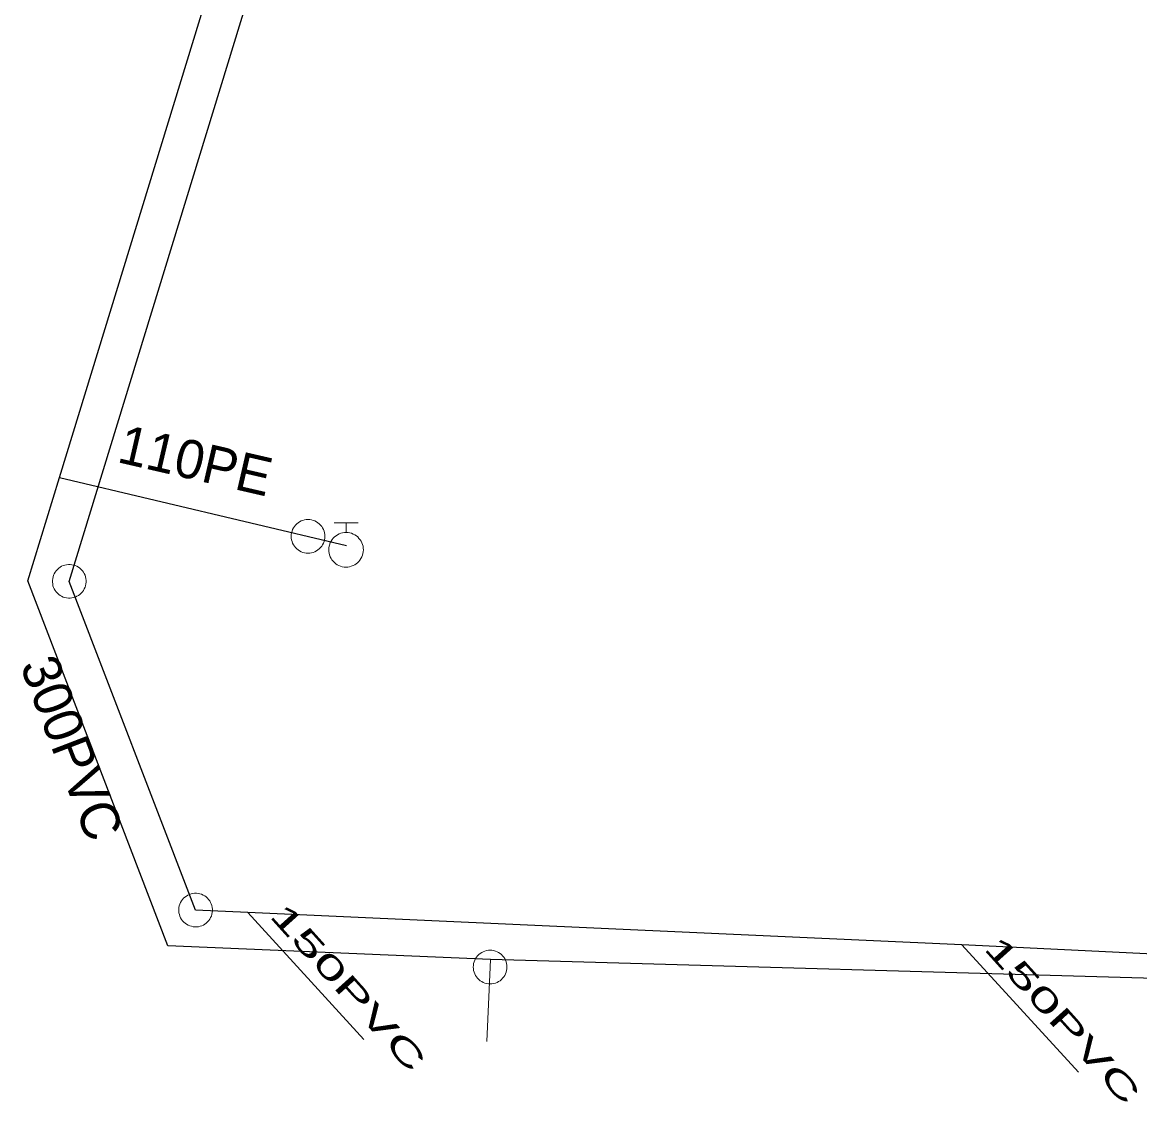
# Model space of a CAD drawing. Extents: x -741806 to -738704, y -1059275 to -1055387.
# Drawn here: x -740348.56 to -740319.54, y -1057396.67 to -1057368.63 of the extents above; entities that cross this region are included whole.
import ezdxf

# ---------------------------------------------------------------- set-up
doc = ezdxf.new("R2010")
doc.units = 0
doc.header["$LTSCALE"] = 0.4
for name, color, linetype, lineweight in [('2', 7, 'Continuous', 25), ('21', 7, 'Continuous', 13), ('3', 7, 'Continuous', 13), ('50', 7, 'Continuous', 13), ('51', 7, 'Continuous', 13), ('52', 7, 'Continuous', 25), ('56', 7, 'Continuous', 13)]:
    doc.layers.add(name, color=color, linetype=linetype, lineweight=lineweight)
for name, color, linetype in [('5', 7, 'Continuous'), ('53', 7, 'Continuous'), ('55', 7, 'Continuous')]:
    doc.layers.add(name, color=color, linetype=linetype)

msp = doc.modelspace()

# ---------------------------------------------------------------- linework, layer by layer
at = {"layer": '2'}
msp.add_line((-740344.059, -1057391.69), (-740347.34, -1057383.149), dxfattribs=at)
for points in [[(-740347.34, -1057383.149), (-740338.066, -1057352.864), (-740334.91, -1057342.56), (-740333.19, -1057336.94)], [(-740274.71, -1057394.48), (-740280.23, -1057394.279), (-740283.993, -1057394.142), (-740292.598, -1057393.83), (-740297.616, -1057393.647), (-740304.263, -1057393.406), (-740316.522, -1057392.96), (-740324.158, -1057392.594), (-740342.703, -1057391.752), (-740344.059, -1057391.69)]]:
    msp.add_lwpolyline(points, dxfattribs=at)
at = {"layer": '21'}
msp.add_lwpolyline([(-740336.401, -1057392.97), (-740336.41, -1057393.169), (-740336.495, -1057395.105)], dxfattribs=at)
at = {"layer": '3'}
for points in [[(-740347.496, -1057382.739), (-740347.537, -1057382.758), (-740347.577, -1057382.781), (-740347.614, -1057382.808), (-740347.648, -1057382.838), (-740347.678, -1057382.873), (-740347.706, -1057382.91), (-740347.728, -1057382.95), (-740347.747, -1057382.991), (-740347.761, -1057383.035), (-740347.77, -1057383.079), (-740347.775, -1057383.125), (-740347.776, -1057383.171), (-740347.77, -1057383.216), (-740347.762, -1057383.261), (-740347.747, -1057383.305), (-740347.729, -1057383.347), (-740347.705, -1057383.386), (-740347.679, -1057383.423), (-740347.648, -1057383.458), (-740347.613, -1057383.488), (-740347.576, -1057383.515), (-740347.538, -1057383.537), (-740347.495, -1057383.556), (-740347.452, -1057383.571), (-740347.407, -1057383.58), (-740347.361, -1057383.584), (-740347.316, -1057383.585), (-740347.27, -1057383.58), (-740347.225, -1057383.571), (-740347.181, -1057383.556), (-740347.14, -1057383.538), (-740347.101, -1057383.515), (-740347.063, -1057383.488), (-740347.029, -1057383.457), (-740346.999, -1057383.424), (-740346.971, -1057383.386), (-740346.949, -1057383.347), (-740346.93, -1057383.304), (-740346.916, -1057383.261), (-740346.907, -1057383.217), (-740346.902, -1057383.171), (-740346.901, -1057383.125), (-740346.906, -1057383.079), (-740346.916, -1057383.035), (-740346.93, -1057382.991), (-740346.949, -1057382.949), (-740346.971, -1057382.91), (-740346.998, -1057382.873), (-740347.029, -1057382.839), (-740347.064, -1057382.808), (-740347.101, -1057382.781), (-740347.14, -1057382.758), (-740347.182, -1057382.74), (-740347.225, -1057382.725), (-740347.27, -1057382.716), (-740347.316, -1057382.711), (-740347.361, -1057382.711), (-740347.408, -1057382.716), (-740347.452, -1057382.726), (-740347.495, -1057382.739)], [(-740344.496, -1057391.669), (-740344.495, -1057391.714), (-740344.49, -1057391.759), (-740344.48, -1057391.805), (-740344.466, -1057391.848), (-740344.447, -1057391.889), (-740344.424, -1057391.93), (-740344.396, -1057391.966), (-740344.366, -1057392), (-740344.331, -1057392.03), (-740344.295, -1057392.057), (-740344.255, -1057392.079), (-740344.212, -1057392.098), (-740344.169, -1057392.111), (-740344.124, -1057392.121), (-740344.078, -1057392.126), (-740344.032, -1057392.126), (-740343.987, -1057392.12), (-740343.943, -1057392.111), (-740343.899, -1057392.096), (-740343.857, -1057392.077), (-740343.818, -1057392.053), (-740343.782, -1057392.027), (-740343.747, -1057391.996), (-740343.717, -1057391.962), (-740343.69, -1057391.924), (-740343.668, -1057391.884), (-740343.649, -1057391.843), (-740343.635, -1057391.798), (-740343.626, -1057391.754), (-740343.622, -1057391.708), (-740343.622, -1057391.663), (-740343.627, -1057391.618), (-740343.637, -1057391.572), (-740343.652, -1057391.528), (-740343.67, -1057391.488), (-740343.693, -1057391.447), (-740343.72, -1057391.411), (-740343.752, -1057391.377), (-740343.786, -1057391.347), (-740343.822, -1057391.32), (-740343.862, -1057391.298), (-740343.905, -1057391.279), (-740343.948, -1057391.265), (-740343.993, -1057391.256), (-740344.038, -1057391.251), (-740344.085, -1057391.251), (-740344.13, -1057391.256), (-740344.174, -1057391.266), (-740344.218, -1057391.281), (-740344.26, -1057391.3), (-740344.299, -1057391.324), (-740344.336, -1057391.35), (-740344.37, -1057391.381), (-740344.4, -1057391.415), (-740344.427, -1057391.453), (-740344.45, -1057391.493), (-740344.468, -1057391.534), (-740344.482, -1057391.579), (-740344.491, -1057391.623), (-740344.496, -1057391.668)]]:
    msp.add_lwpolyline(points, dxfattribs=at)
at = {"layer": '50'}
for p in [(-740340.459, -1057381.626), (-740340.151, -1057381.879), (-740339.84, -1057381.626)]:
    msp.add_line(p, (-740340.151, -1057381.626), dxfattribs=at)
msp.add_lwpolyline([(-740339.703, -1057382.333), (-740339.704, -1057382.284), (-740339.711, -1057382.239), (-740339.723, -1057382.192), (-740339.738, -1057382.149), (-740339.757, -1057382.107), (-740339.784, -1057382.067), (-740339.816, -1057382.032), (-740339.847, -1057381.996), (-740339.884, -1057381.965), (-740339.925, -1057381.941), (-740339.966, -1057381.919), (-740340.008, -1057381.9), (-740340.054, -1057381.891), (-740340.101, -1057381.882), (-740340.147, -1057381.879), (-740340.192, -1057381.882), (-740340.24, -1057381.886), (-740340.287, -1057381.9), (-740340.329, -1057381.918), (-740340.374, -1057381.938), (-740340.412, -1057381.963), (-740340.45, -1057381.993), (-740340.483, -1057382.027), (-740340.512, -1057382.062), (-740340.539, -1057382.101), (-740340.56, -1057382.142), (-740340.577, -1057382.187), (-740340.593, -1057382.232), (-740340.597, -1057382.279), (-740340.602, -1057382.325), (-740340.6, -1057382.374), (-740340.593, -1057382.421), (-740340.581, -1057382.464), (-740340.565, -1057382.51), (-740340.542, -1057382.551), (-740340.519, -1057382.591), (-740340.487, -1057382.627), (-740340.456, -1057382.661), (-740340.418, -1057382.692), (-740340.38, -1057382.717), (-740340.335, -1057382.739), (-740340.293, -1057382.755), (-740340.249, -1057382.769), (-740340.2, -1057382.777), (-740340.153, -1057382.78), (-740340.106, -1057382.777), (-740340.062, -1057382.769), (-740340.016, -1057382.757), (-740339.971, -1057382.741), (-740339.928, -1057382.719), (-740339.889, -1057382.695), (-740339.852, -1057382.665), (-740339.819, -1057382.633), (-740339.79, -1057382.597), (-740339.765, -1057382.556), (-740339.739, -1057382.515), (-740339.724, -1057382.472), (-740339.712, -1057382.425), (-740339.704, -1057382.38)], close=True, dxfattribs=at)
at = {"layer": '51'}
for points in [[(-740340.701, -1057381.98), (-740340.703, -1057381.935), (-740340.711, -1057381.89), (-740340.723, -1057381.845), (-740340.739, -1057381.803), (-740340.76, -1057381.762), (-740340.784, -1057381.723), (-740340.814, -1057381.688), (-740340.846, -1057381.655), (-740340.882, -1057381.627), (-740340.919, -1057381.602), (-740340.961, -1057381.581), (-740341.004, -1057381.564), (-740341.048, -1057381.552), (-740341.093, -1057381.545), (-740341.139, -1057381.543), (-740341.184, -1057381.545), (-740341.23, -1057381.552), (-740341.274, -1057381.564), (-740341.316, -1057381.581), (-740341.358, -1057381.602), (-740341.396, -1057381.627), (-740341.431, -1057381.655), (-740341.463, -1057381.688), (-740341.493, -1057381.723), (-740341.517, -1057381.762), (-740341.539, -1057381.803), (-740341.554, -1057381.845), (-740341.566, -1057381.89), (-740341.574, -1057381.935), (-740341.576, -1057381.981), (-740341.574, -1057382.026), (-740341.566, -1057382.071), (-740341.554, -1057382.116), (-740341.539, -1057382.158), (-740341.517, -1057382.199), (-740341.493, -1057382.238), (-740341.463, -1057382.273), (-740341.431, -1057382.306), (-740341.396, -1057382.334), (-740341.358, -1057382.359), (-740341.316, -1057382.38), (-740341.274, -1057382.397), (-740341.23, -1057382.408), (-740341.184, -1057382.416), (-740341.139, -1057382.418), (-740341.093, -1057382.416), (-740341.048, -1057382.408), (-740341.004, -1057382.397), (-740340.961, -1057382.38), (-740340.919, -1057382.359), (-740340.882, -1057382.334), (-740340.846, -1057382.306), (-740340.814, -1057382.273), (-740340.784, -1057382.238), (-740340.76, -1057382.199), (-740340.739, -1057382.158), (-740340.723, -1057382.116), (-740340.711, -1057382.071), (-740340.703, -1057382.026), (-740340.701, -1057381.981)], [(-740335.973, -1057393.169), (-740335.975, -1057393.124), (-740335.982, -1057393.079), (-740335.994, -1057393.034), (-740336.01, -1057392.992), (-740336.031, -1057392.951), (-740336.056, -1057392.912), (-740336.085, -1057392.877), (-740336.117, -1057392.844), (-740336.153, -1057392.816), (-740336.191, -1057392.791), (-740336.232, -1057392.77), (-740336.275, -1057392.753), (-740336.319, -1057392.741), (-740336.364, -1057392.734), (-740336.41, -1057392.732), (-740336.456, -1057392.734), (-740336.501, -1057392.741), (-740336.545, -1057392.753), (-740336.588, -1057392.77), (-740336.629, -1057392.791), (-740336.667, -1057392.816), (-740336.703, -1057392.844), (-740336.735, -1057392.877), (-740336.764, -1057392.912), (-740336.789, -1057392.951), (-740336.81, -1057392.992), (-740336.826, -1057393.034), (-740336.838, -1057393.079), (-740336.845, -1057393.124), (-740336.848, -1057393.17), (-740336.845, -1057393.215), (-740336.838, -1057393.26), (-740336.826, -1057393.305), (-740336.81, -1057393.347), (-740336.789, -1057393.388), (-740336.764, -1057393.427), (-740336.735, -1057393.462), (-740336.703, -1057393.495), (-740336.667, -1057393.523), (-740336.629, -1057393.548), (-740336.588, -1057393.569), (-740336.545, -1057393.586), (-740336.501, -1057393.597), (-740336.456, -1057393.605), (-740336.41, -1057393.607), (-740336.364, -1057393.605), (-740336.319, -1057393.597), (-740336.275, -1057393.586), (-740336.232, -1057393.569), (-740336.191, -1057393.548), (-740336.153, -1057393.523), (-740336.117, -1057393.495), (-740336.085, -1057393.462), (-740336.056, -1057393.427), (-740336.031, -1057393.388), (-740336.01, -1057393.347), (-740335.994, -1057393.305), (-740335.982, -1057393.26), (-740335.975, -1057393.215), (-740335.973, -1057393.17)]]:
    msp.add_lwpolyline(points, dxfattribs=at)
at = {"layer": '52'}
msp.add_line((-740347.592, -1057380.453), (-740340.138, -1057382.217), dxfattribs=at)
msp.add_lwpolyline([(-740249.71, -1057396.29), (-740253.596, -1057395.887), (-740273.502, -1057395.585), (-740279.574, -1057395.223), (-740280.318, -1057395.179), (-740284.998, -1057395.12), (-740299.727, -1057394.348), (-740308.203, -1057393.86), (-740318.232, -1057393.49), (-740336.401, -1057392.97), (-740344.776, -1057392.614), (-740348.414, -1057383.139), (-740347.592, -1057380.453), (-740341.638, -1057360.999), (-740337.881, -1057348.652), (-740336.432, -1057343.803), (-740328.93, -1057319.611), (-740321.949, -1057297.29), (-740319.561, -1057289.659), (-740319.489, -1057289.497)], dxfattribs=at)
at = {"layer": '56'}
for p, q in [((-740339.693, -1057395.048), (-740342.703, -1057391.752)), ((-740321.136, -1057395.902), (-740324.158, -1057392.594))]:
    msp.add_line(p, q, dxfattribs=at)

# ---------------------------------------------------------------- texts
at = {"layer": '5'}
msp.add_text('300PVC', height=1, rotation=291, dxfattribs=at).set_placement((-740348.628, -1057385.33))
at = {"layer": '53'}
msp.add_text('110PE ', height=1, rotation=347, dxfattribs=at).set_placement((-740346.128, -1057380.044))
at = {"layer": '55', "width": 1.85}
for p in [(-740342.167, -1057391.847), (-740323.616, -1057392.695)]:
    msp.add_text('150PVC', height=0.6, rotation=312, dxfattribs=at).set_placement(p)

doc.saveas('drawing.dxf')
